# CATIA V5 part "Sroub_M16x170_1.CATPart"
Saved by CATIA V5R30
Part number: Sroub_M16x170_1
Definition: E 1200_16x170_2
Nomenclature: E 1200_16x170_2
Source: Unknown
Description: PART--DESC
Bounding box of the stored display mesh (mm): x -152 to -128, y 125.01 to 148.99, z -259 to -73
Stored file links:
  E:\Bakalarka\Model\Forma_v7\Sroub_M16x170_1.CATPart
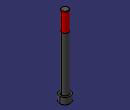
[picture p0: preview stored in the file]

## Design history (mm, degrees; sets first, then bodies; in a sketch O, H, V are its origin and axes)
Body1 "MANIFOLD_SOLID_BREP #3794" (main body)
  Solid1: solid without history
